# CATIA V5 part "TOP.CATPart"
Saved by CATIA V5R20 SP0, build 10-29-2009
Part number: TOP
Bounding box of the stored display mesh (mm): x 0 to 12, y -332.652 to 332.652, z -332.652 to 332.652
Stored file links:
  C:\Users\Dell\Desktop\Documentations\week8 doc\TOP.CATPart
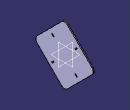
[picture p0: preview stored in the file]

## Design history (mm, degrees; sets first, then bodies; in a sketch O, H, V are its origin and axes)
Body1 (main body)
  Sketch1 on yz-plane, origin (0, 0, 0), H (0, 1, 0), V (0, 0, 1)
    line L1 (-35.3553, 318.1981) -> (-318.1981, 35.3553)
    point P1 (0, 353.5534)
    point P2 (-353.5534, 0)
    line L2 (-318.1981, -35.3553) -> (-35.3553, -318.1981)
    point P3 (0, -353.5534)
    axis line L3 (0, 42.4636) -> (0, -46.4624)
    point P4 (0, 42.4636)
    point P6 (353.5534, 0)
    point P7 (0, 353.5534)
    line L4 (35.3553, 318.1981) -> (318.1981, 35.3553)
    point P8 (0, -353.5534)
    line L5 (318.1981, -35.3553) -> (35.3553, -318.1981)
    arc A1 centre (0, 282.8427) radius 50 from (-35.3553, 318.1981) to (35.3553, 318.1981) cw
    point P11 (0, 282.8427)
    arc A2 centre (-282.8427, 0) radius 50 from (-318.1981, 35.3553) to (-318.1981, -35.3553) ccw
    arc A3 centre (282.8427, 0) radius 50 from (318.1981, 35.3553) to (318.1981, -35.3553) cw
    arc A4 centre (0, -282.8427) radius 50 from (-35.3553, -318.1981) to (35.3553, -318.1981) ccw
    angle L1 L2 = 90
    distance P1 P2 = 500
    radius A1 = 50
    distance P2 P3 = 500
    radius A2 = 50
    radius A3 = 50
    radius A4 = 50
    coincidence: P1 V, P2 H, P3 V, P4 V, L1 P1, L4 P7, P11 L3, L1 P2, L2 P2, L4 P6, L5 P6, L2 P3, L5 P8
    vertical: L3 V
    symmetry: P2 P6 L3, P1 P7 L3, L1 L4 L3, P3 P8 L3, L2 L5 L3
    tangency: A1 L1, A1 L4, A2 L1, A2 L2, A3 L4, A3 L5, A4 L2, A4 L5
  Pad1: profile Sketch1, direction (1, 0, 0), length 12
  Sketch2 on start face of Pad1, origin (0, 0, 0), H (0, -1, 0), V (0, 0, 1)
    construction line L1 (0, 398.7279) -> (0, -442.8403)
    point P1 (0, 398.7279)
    construction line L2 (757.5255, 0) -> (-746.2007, 0)
    point P3 (757.5255, 0)
    construction line L3 (398.9939, 398.9939) -> (-474.7871, -474.7871)
    line L4 (-128.057, 119.4303) -> (-149.4117, 140.785)
    point P7 (-128.057, 119.4303)
    point P8 (-149.4117, 140.785)
    line L5 (-149.4117, 140.785) -> (-140.785, 149.4117)
    point P9 (-149.4117, 140.785)
    point P10 (-140.785, 149.4117)
    line L6 (-140.785, 149.4117) -> (-119.4303, 128.057)
    point P11 (-140.785, 149.4117)
    point P12 (-119.4303, 128.057)
    line L7 (-119.4303, 128.057) -> (-128.057, 119.4303)
    point P13 (-128.057, 119.4303)
    point P14 (-119.4303, 128.057)
    axis line L8 (-40.0012, 40.0012) -> (0, 0)
    point P16 (0, 0)
    point P17 (128.057, 119.4303)
    point P18 (149.4117, 140.785)
    point P19 (149.4117, 140.785)
    point P20 (140.785, 149.4117)
    point P21 (140.785, 149.4117)
    point P22 (119.4303, 128.057)
    point P23 (128.057, 119.4303)
    point P24 (119.4303, 128.057)
    line L9 (128.057, 119.4303) -> (149.4117, 140.785)
    line L10 (149.4117, 140.785) -> (140.785, 149.4117)
    line L11 (140.785, 149.4117) -> (119.4303, 128.057)
    line L12 (119.4303, 128.057) -> (128.057, 119.4303)
    point P25 (-128.057, -119.4303)
    point P26 (-149.4117, -140.785)
    point P27 (-149.4117, -140.785)
    point P28 (-140.785, -149.4117)
    point P29 (-140.785, -149.4117)
    point P30 (-119.4303, -128.057)
    point P31 (-128.057, -119.4303)
    point P32 (-119.4303, -128.057)
    point P33 (128.057, -119.4303)
    point P34 (149.4117, -140.785)
    point P35 (149.4117, -140.785)
    point P36 (140.785, -149.4117)
    point P37 (140.785, -149.4117)
    point P38 (119.4303, -128.057)
    point P39 (128.057, -119.4303)
    point P40 (119.4303, -128.057)
    line L13 (-128.057, -119.4303) -> (-149.4117, -140.785)
    line L14 (-149.4117, -140.785) -> (-140.785, -149.4117)
    line L15 (-140.785, -149.4117) -> (-119.4303, -128.057)
    line L16 (-119.4303, -128.057) -> (-128.057, -119.4303)
    line L17 (128.057, -119.4303) -> (149.4117, -140.785)
    line L18 (149.4117, -140.785) -> (140.785, -149.4117)
    line L19 (140.785, -149.4117) -> (119.4303, -128.057)
    line L20 (119.4303, -128.057) -> (128.057, -119.4303)
    length L6 = 30.2
    length L4 = 30.2
    length L5 = 12.2
    distance L6 L8 = 6.1
    angle L8 L1 = 45
    distance L7 L3 = 175
    coincidence: P1 V, P3 H, L3 O, P9 L4, P11 P10, P13 L4, P16 O, P12 P14
    vertical: L1 V
    horizontal: L2 H
    perpendicularity: L4 L3
    parallelism: L5 L3, L6 L4
    symmetry: P7 P17 L1, P8 P18 L1, P9 P19 L1, P10 P20 L1, P11 P21 L1, P12 P22 L1, P13 P23 L1, P14 P24 L1, L4 L9 L1, L5 L10 L1, L6 L11 L1, L7 L12 L1, P7 P25 L2, P8 P26 L2, P9 P27 L2, P10 P28 L2, P11 P29 L2, P12 P30 L2, P13 P31 L2, P14 P32 L2, P17 P33 L2, P18 P34 L2, P19 P35 L2, P20 P36 L2, P21 P37 L2, P22 P38 L2, P23 P39 L2, P24 P40 L2, L4 L13 L2, L5 L14 L2, L6 L15 L2, L7 L16 L2, L9 L17 L2, L10 L18 L2, L11 L19 L2, L12 L20 L2
  Pocket1: profile Sketch2, direction (1, 0, 0), length 12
